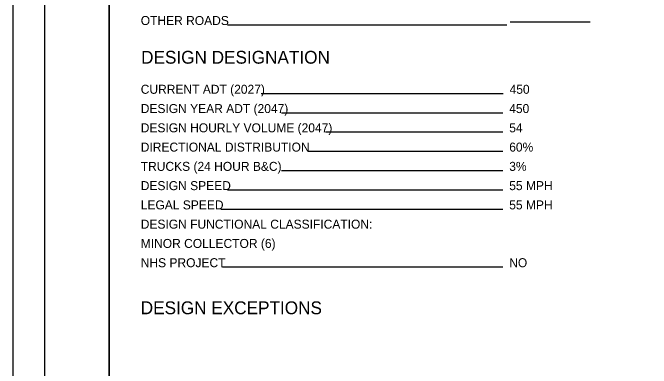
# Model space of a CAD drawing. Extents: x 0 to 44, y -23.8 to 22.
# Drawn here: x 0 to 9.95, y 5.53 to 11.07 of the extents above; entities that cross this region are included whole.
import ezdxf

# ---------------------------------------------------------------- set-up
doc = ezdxf.new("R2010")
doc.units = 0
for name, color, linetype in [('SH_Border', 7, 'Continuous'), ('SH_Cut_Line', 7, 'Continuous'), ('SH_Data', 7, 'Continuous'), ('SH_Text', 7, 'Continuous')]:
    doc.layers.add(name, color=color, linetype=linetype)

msp = doc.modelspace()

# ---------------------------------------------------------------- linework, layer by layer
at = {"layer": 'SH_Border'}
for points in [[(0.5, 21.5), (1.5, 21.5), (1.5, 0.5), (0.5, 0.5)], [(1.5, 21.5), (33.5, 21.5), (33.5, 0.5), (1.5, 0.5)]]:
    msp.add_lwpolyline(points, close=True, dxfattribs=at)
at = {"layer": 'SH_Cut_Line'}
msp.add_lwpolyline([(0, 0), (34, 0), (34, 22), (0, 22)], close=True, dxfattribs=at)
at = {"layer": 'SH_Data'}
for p, q in [((7.7, 10.8767), (3.3471, 10.8767)), ((9, 10.9223), (7.75, 10.9223)), ((7.6424, 9.8062), (3.871, 9.8062)), ((7.6368, 9.5062), (4.1885, 9.5062)), ((7.6368, 9.2062), (4.8723, 9.2062)), ((7.6368, 8.9062), (4.6037, 8.9062)), ((7.6368, 8.6062), (4.1885, 8.6062)), ((7.6368, 8.3062), (3.346, 8.3062)), ((7.6368, 8.0062), (3.2422, 8.0062)), ((7.6368, 7.1062), (3.2669, 7.1062))]:
    msp.add_line(p, q, dxfattribs=at)

# ---------------------------------------------------------------- texts
msp.add_text('DESIGN DESIGNATION', height=0.2, dxfattribs=at).set_placement((2, 10.2747))
at = {"layer": 'SH_Text'}
for s, height, p in [('OTHER ROADS', 0.14, (1.9944, 10.8767)), ('CURRENT ADT (2027)', 0.14, (1.9944, 9.8062)), ('450', 0.14, (7.7424, 9.8062)), ('DESIGN YEAR ADT (2047)', 0.14, (1.9944, 9.5062)), ('450', 0.14, (7.7368, 9.5062)), ('DESIGN HOURLY VOLUME (2047)', 0.14, (1.9944, 9.2062)), ('54', 0.14, (7.7368, 9.2062)), ('DIRECTIONAL DISTRIBUTION', 0.14, (1.9944, 8.9062)), ('60%', 0.14, (7.7368, 8.9062)), ('TRUCKS (24 HOUR B&C)', 0.14, (1.9944, 8.6062)), ('3%', 0.14, (7.7368, 8.6062)), ('DESIGN SPEED', 0.14, (1.9944, 8.3062)), ('55 MPH', 0.14, (7.7368, 8.3062)), ('LEGAL SPEED', 0.14, (1.9944, 8.0062)), ('55 MPH', 0.14, (7.7368, 8.0062)), ('DESIGN FUNCTIONAL CLASSIFICATION:', 0.14, (1.9944, 7.7062)), ('MINOR COLLECTOR (6)', 0.14, (1.9944, 7.4062)), ('NHS PROJECT', 0.14, (1.9944, 7.1062)), ('NO', 0.14, (7.7368, 7.1062)), ('DESIGN EXCEPTIONS', 0.2, (1.9944, 6.3744))]:
    msp.add_text(s, height=height, dxfattribs=at).set_placement(p)

doc.saveas('drawing.dxf')
